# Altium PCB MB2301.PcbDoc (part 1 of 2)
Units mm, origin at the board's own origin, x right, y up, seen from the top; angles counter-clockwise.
Board outline 43 x 51.45 mm, 4 copper layers (Top Layer, Internal 1, Internal 2, Bottom Layer), stack 1.565 mm thick; 103 components, 91 nets, 383 pads, 756 vias.
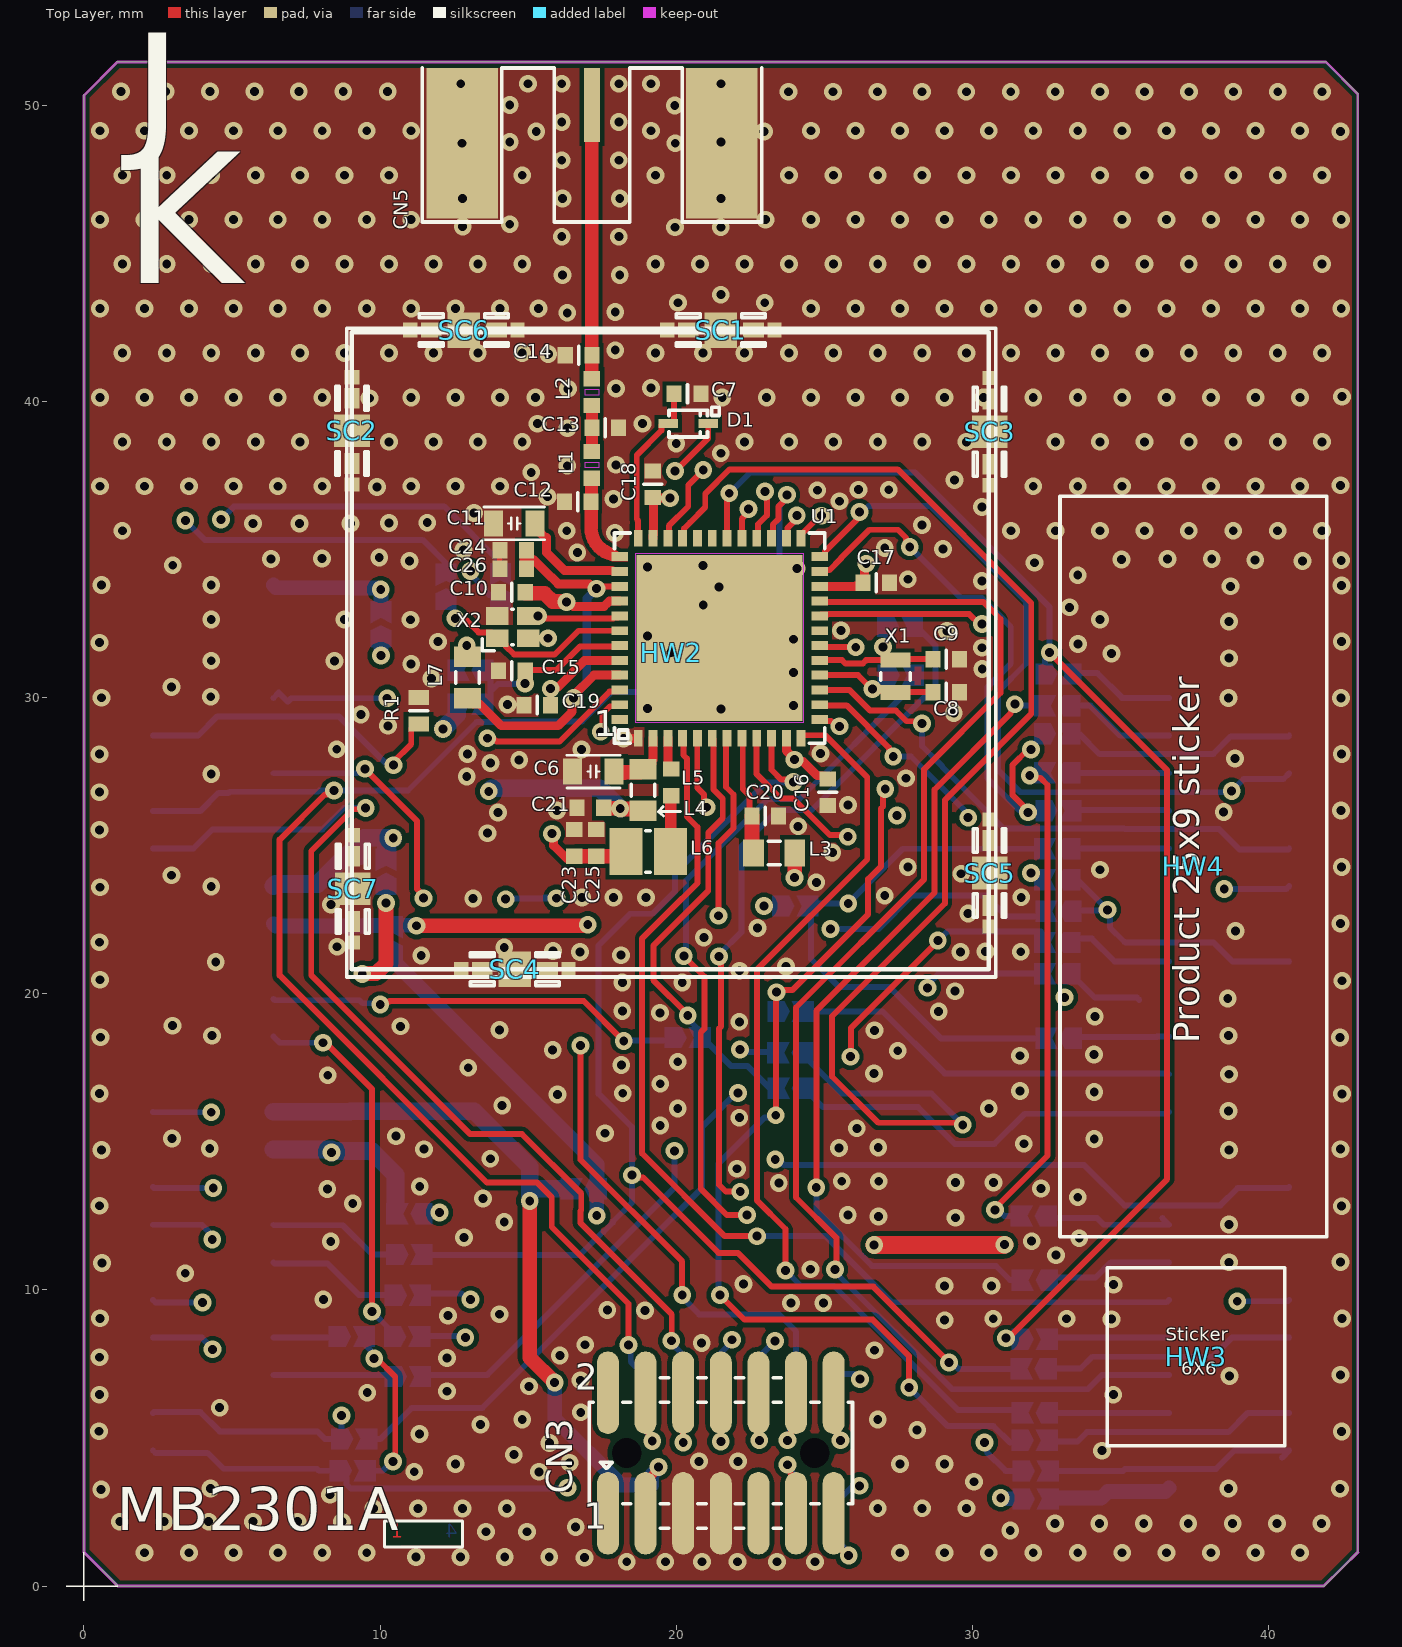
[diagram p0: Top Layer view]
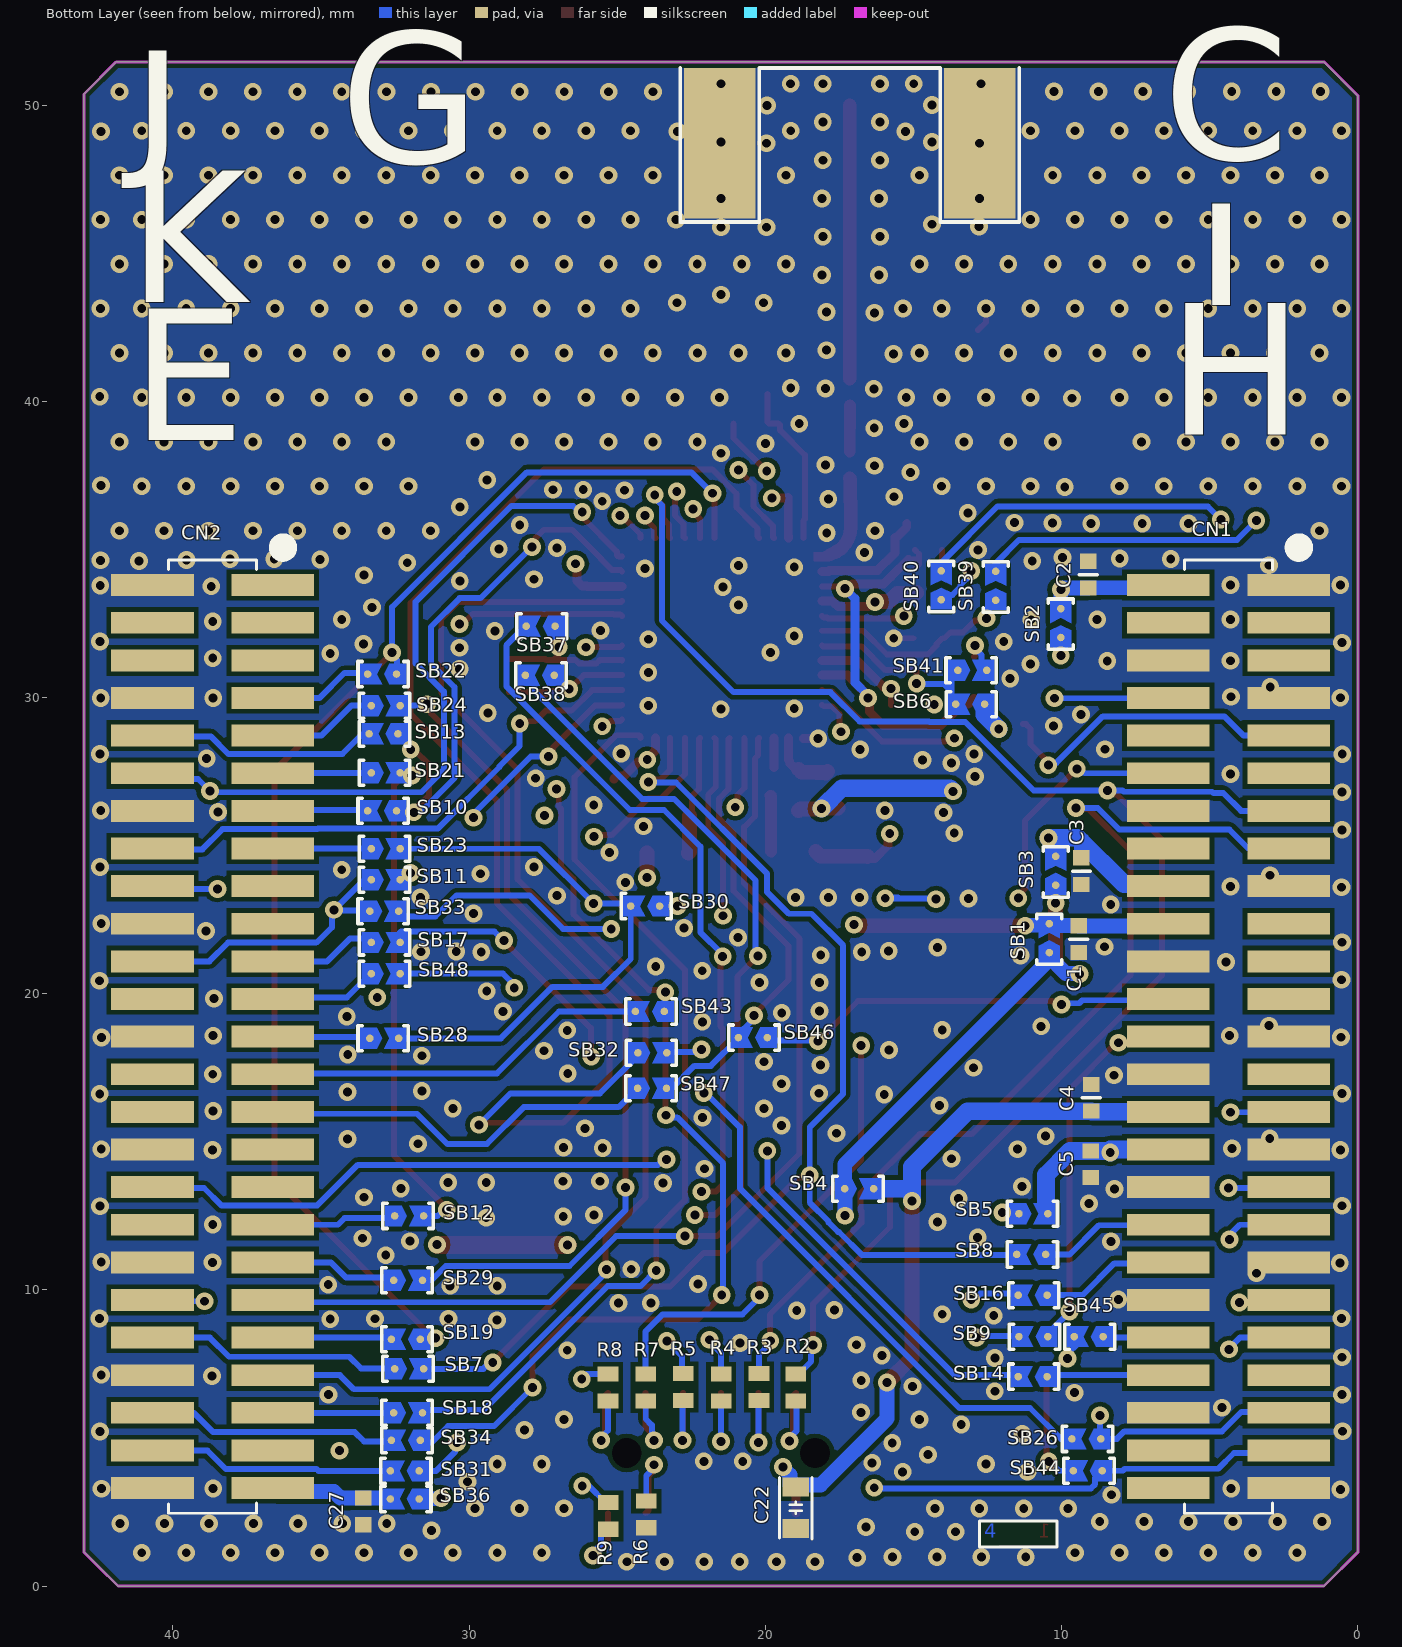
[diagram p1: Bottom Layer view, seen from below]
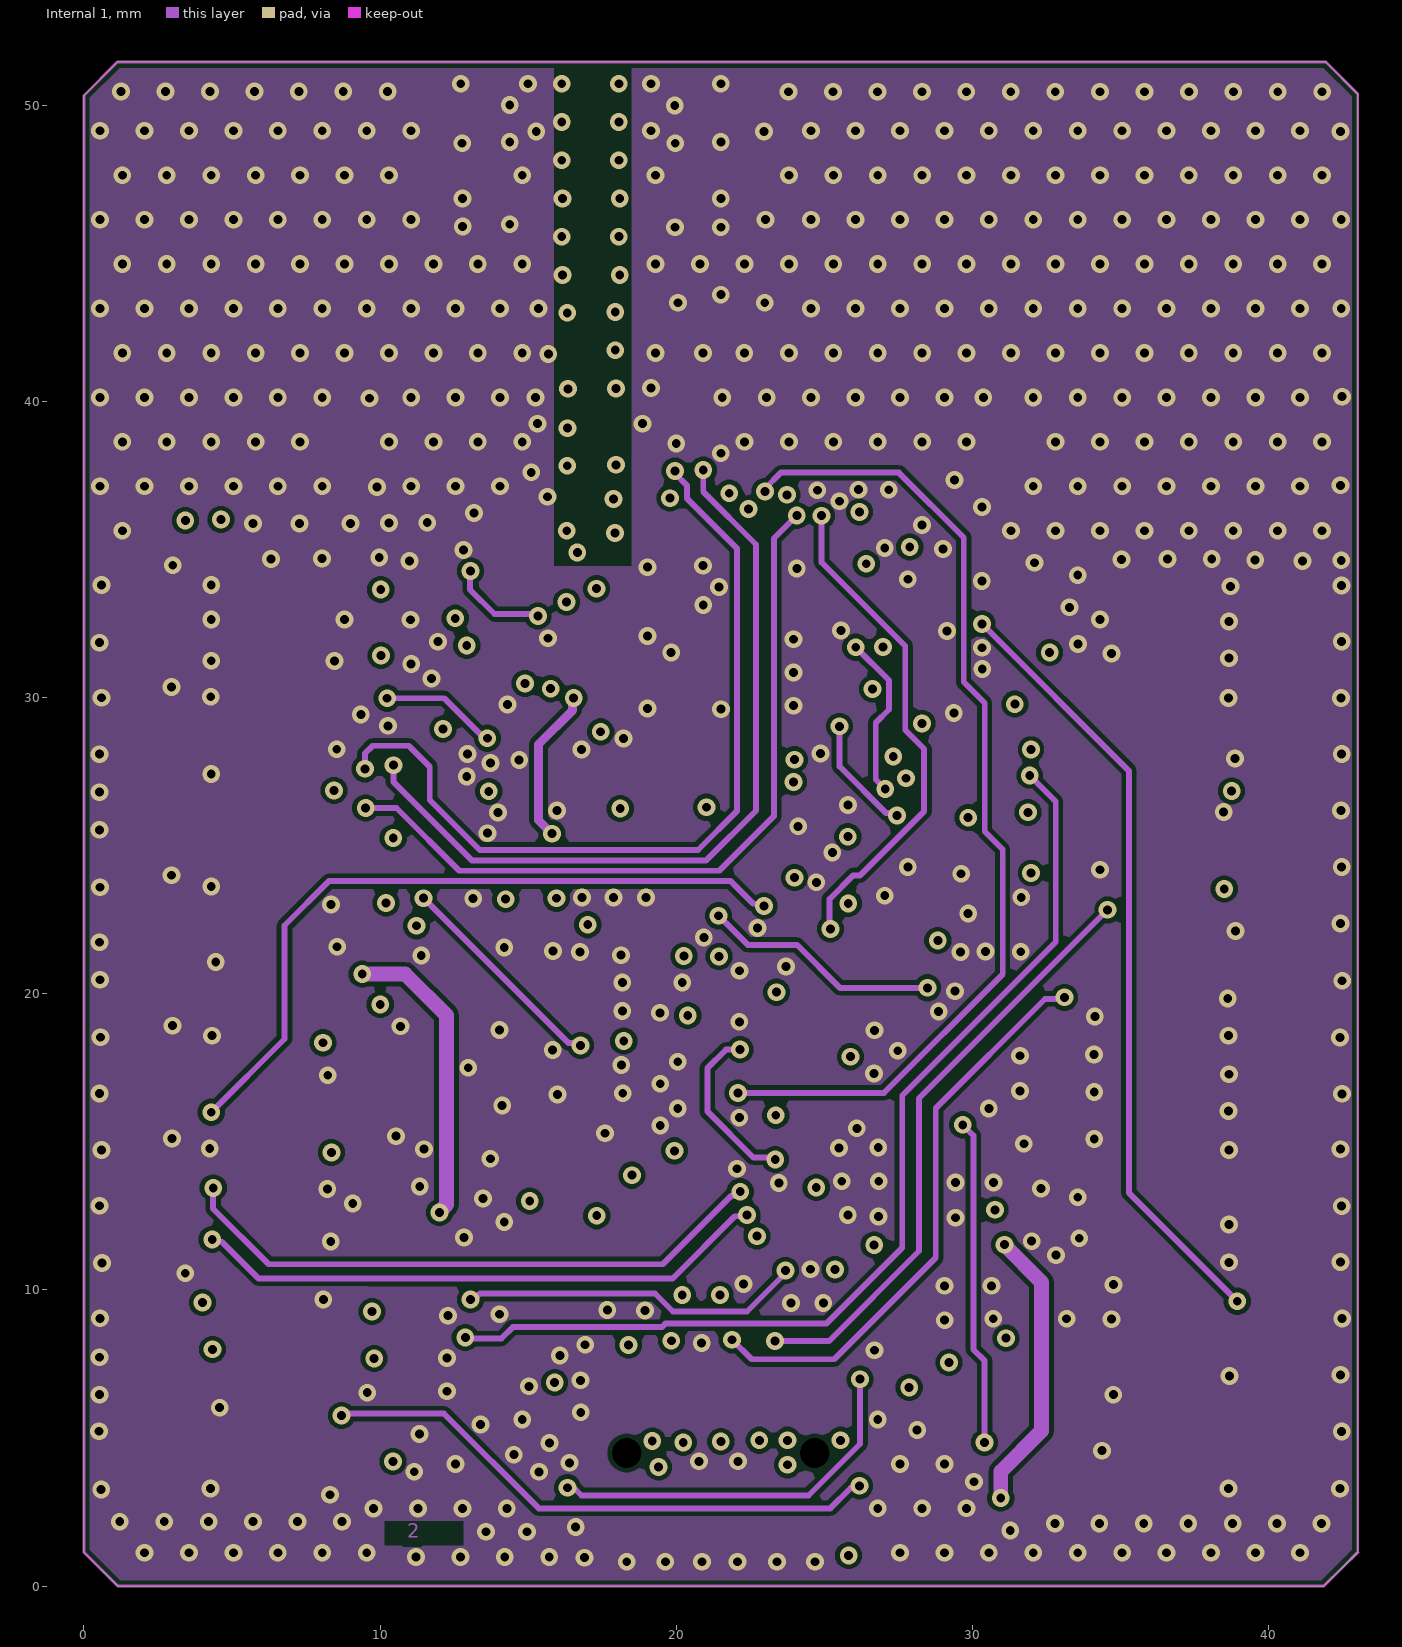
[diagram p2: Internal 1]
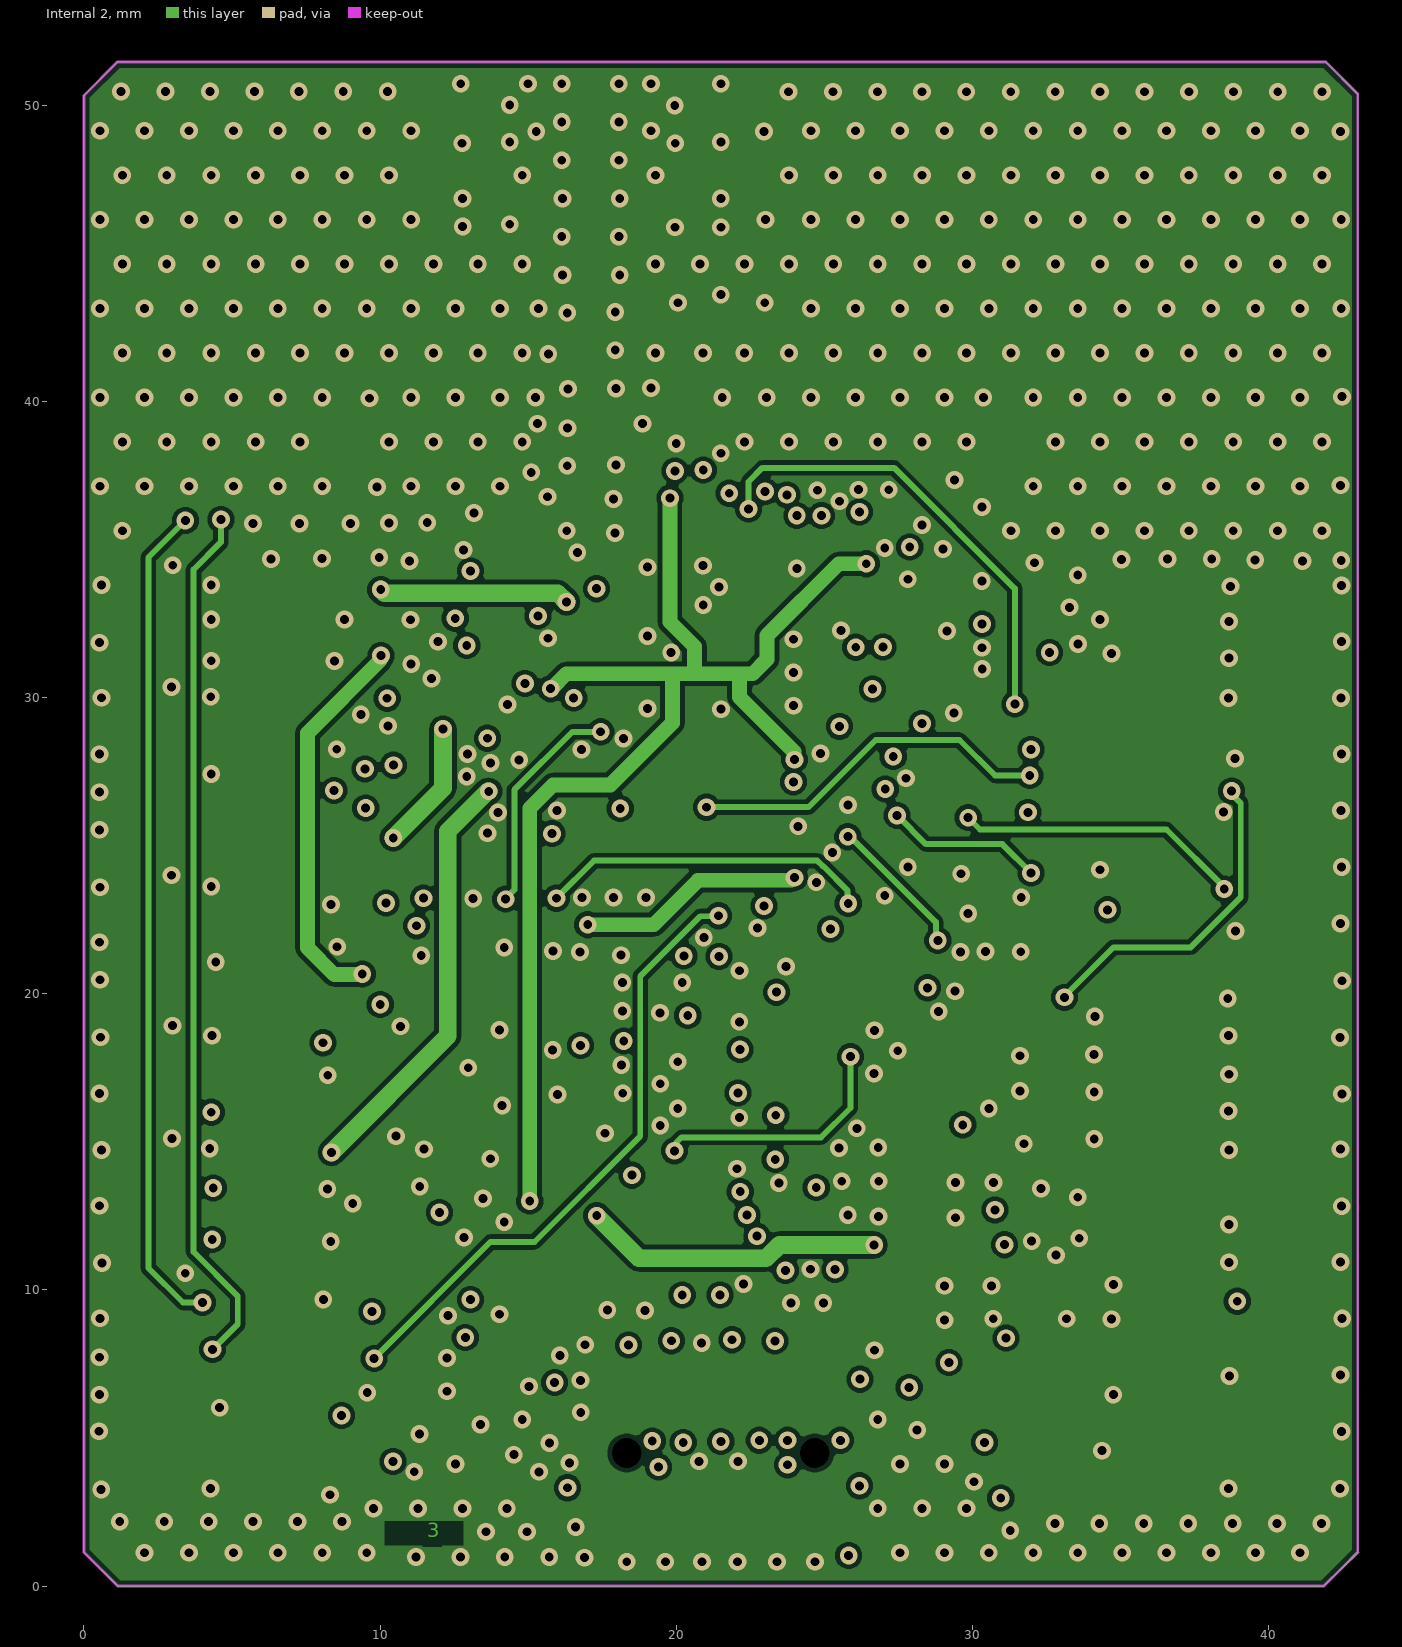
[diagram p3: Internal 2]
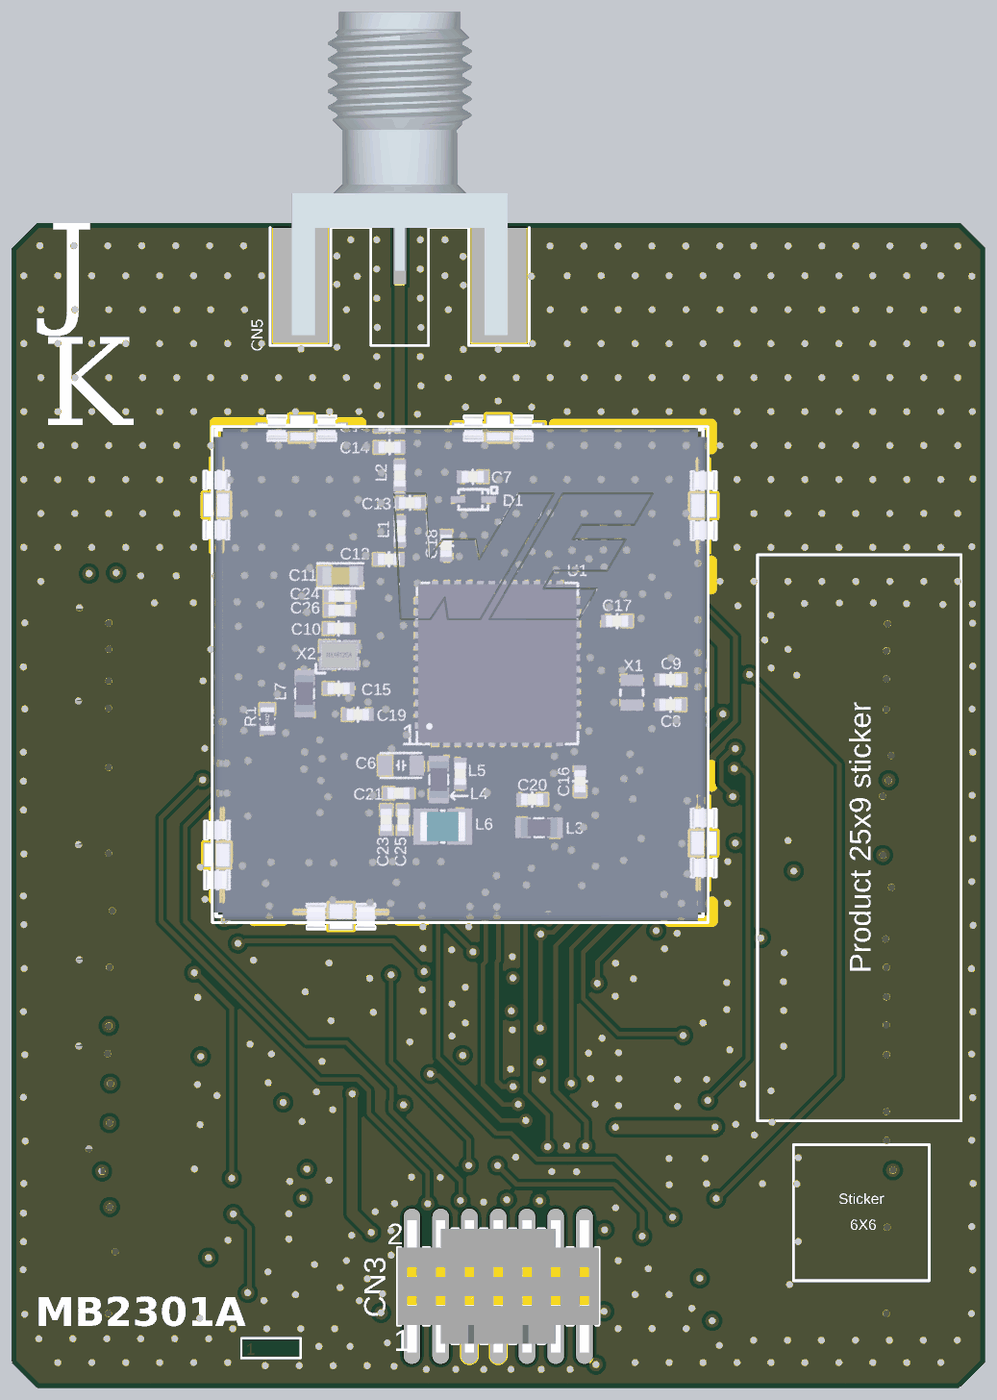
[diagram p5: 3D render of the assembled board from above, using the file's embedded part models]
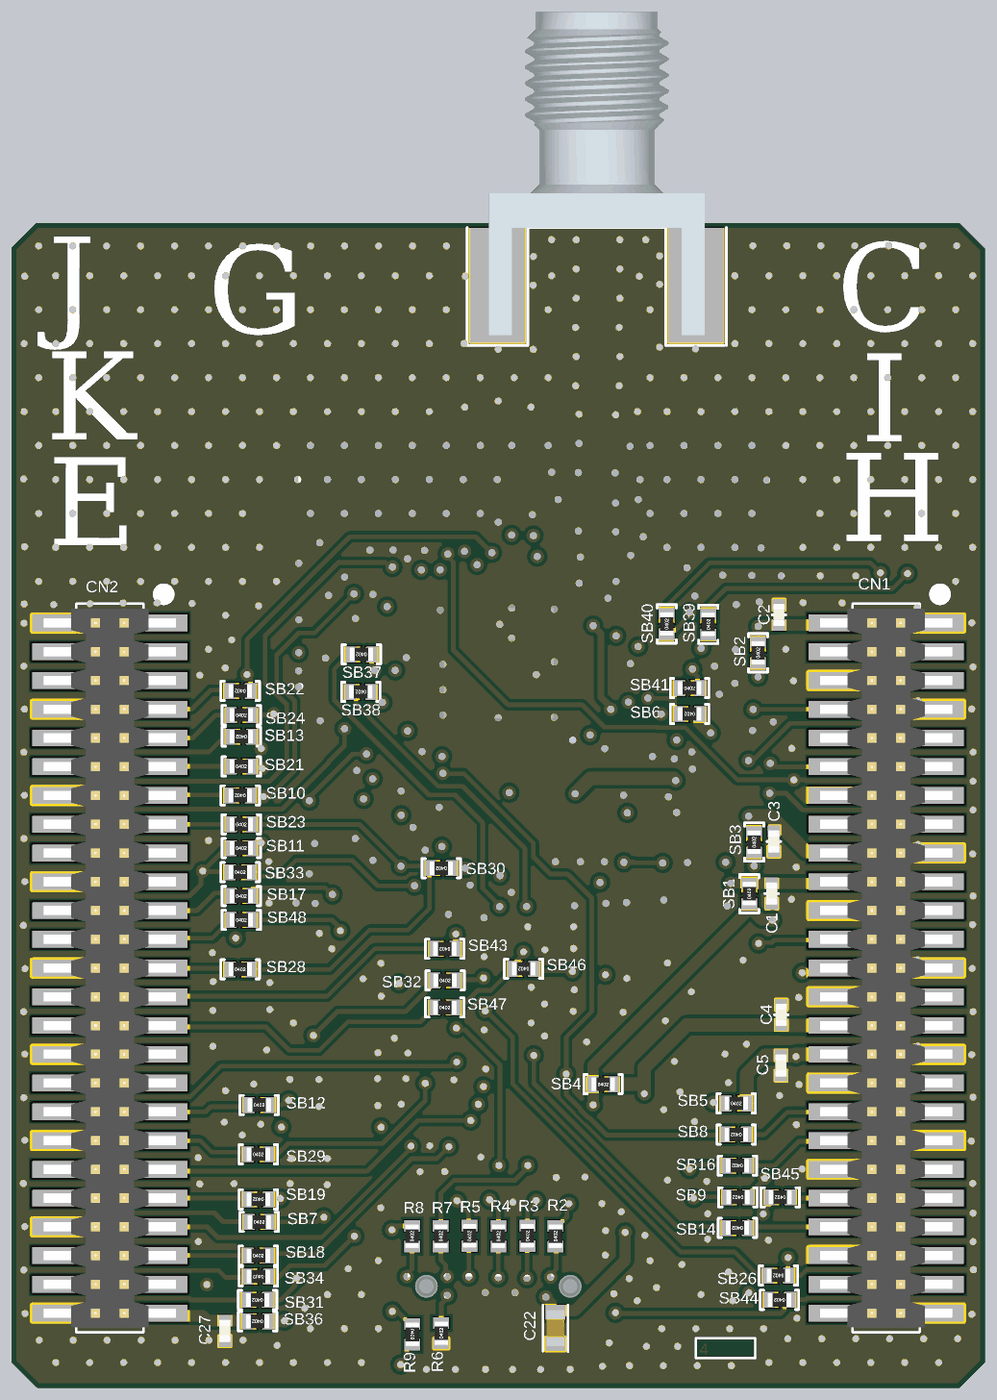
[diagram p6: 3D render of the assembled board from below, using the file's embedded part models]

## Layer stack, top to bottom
Top Solder: solder mask 0.0178, Solder Resist, Dk 4.2
Top Layer: signal copper 0.0406
Dielectric 1: prepreg 0.0762, FR-4, Dk 3.7
Internal 1: signal copper 0.0305
Dielectric 3: core 1.27, FR-4, Dk 4.5
Internal 2: signal copper 0.0305
Dielectric 2: prepreg 0.0762, FR-4, Dk 3.7
Bottom Layer: signal copper 0.0406
Bottom Solder: solder mask 0.0178, Solder Resist, Dk 4.2

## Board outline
0.001,1.143 0.001,50.3 0.001,50.324 1.132,51.455 41.913,51.455 43.001,50.367 43.001,39.986 43.002,1.145 41.852,0.005 1.139,0.005

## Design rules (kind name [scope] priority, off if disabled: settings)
Clearance RF [All vs (ObjectKind = 'Track') And (Net = 'NetC14_1') Or (Net = 'NetC13_2') Or (Net = 'NetC12_1')] p1: gap=0.13 ignorepadtopadclearanceinfootprint=FALSE
Clearance [All] p2: gap=0.15 ignorepadtopadclearanceinfootprint=FALSE
ComponentClearance [Not InComponent('HW2') vs Not InComponent('SC1') and InComponent('SC2') and InComponent('SC3') and InComponent('SC4') and InComponent('SC5')] p1: gap=0.2 collisioncheckmode=3 verticalgap=0.2 showdistances=FALSE
DiffPairsRouting [All] p1: maxlimit=0.254 minlimit=0.15 mostfreqgap=0.226 toplayer_minwidth=0.155 toplayer_maxwidth=0.226 toplayer_prefwidth=0.155 midlayer1_prefgap=0.15 midlayer1_minwidth=0.083 midlayer1_maxwidth=0.127 midlayer1_prefwidth=0.1 midlayer2_prefgap=0.15 midlayer2_minwidth=0.083 midlayer2_maxwidth=0.127 midlayer2_prefwidth=0.1 bottomlayer_minwidth=0.155 bottomlayer_maxwidth=0.226 bottomlayer_prefwidth=0.155 maxuncoupledlength=12.7
HoleSize [All] p1: absolutevalues=TRUE maxlimit=10 minlimit=0.025 maxpercent=80.000 minpercent=20.000
LayerPairs [All] p1 off: enforce=TRUE
MinimumSolderMaskSliver [All] p1 off: minsoldermaskwidth=0.1
PasteMaskExpansion [All] p1 off: expansion=0
PlaneConnect [All] p1: planeconnectstyle=Relief reliefexpansion=0.508 reliefentries=4 reliefconductorwidth=0.21 reliefairgap=0.21
PolygonConnect Path_RF [InNet('NetC12_2')] p1: connectstyle=Direct reliefconductorwidth=0.254 reliefentries=4 polygonreliefangle="90 Angle" airgapwidth=0.254
PolygonConnect PolygonConnect_via [IsVia] p2: connectstyle=Direct reliefconductorwidth=0.254 reliefentries=4 polygonreliefangle="90 Angle" airgapwidth=0.254
PolygonConnect General [All] p3: connectstyle=Direct reliefconductorwidth=0.2 reliefentries=4 polygonreliefangle="90 Angle" airgapwidth=0.2
RoutingVias [All] p1: holewidth=0.3 width=0.8 viastyle="Through Hole" minholewidth=0.2 minwidth=0.5 maxholewidth=3.5 maxwidth=6.5
SilkToSilkClearance [All] p1 off: silktosilkclearance=0.2
SilkToSolderMaskClearance [IsPad] p1 off: minsilkscreentomaskgap=0.2 clearancetoexposedcopper=TRUE
SolderMaskExpansion [All] p1: expansion=0.102 istentingtop=FALSE
SupplyNets "Schematic Supply Nets_6" [InNet('VDD3')] p1: voltage=0.000
SupplyNets "Schematic Supply Nets_5" [InNet('VDDA')] p2: voltage=0.000
SupplyNets "Schematic Supply Nets_4" [InNet('GND')] p3: voltage=0.000
SupplyNets "Schematic Supply Nets_3" [InNet('VDD1')] p4: voltage=0.000
SupplyNets "Schematic Supply Nets_2" [InNet('VDD14')] p5: voltage=0.000
SupplyNets "Schematic Supply Nets_1" [InNet('VDD4')] p6: voltage=0.000
SupplyNets "Schematic Supply Nets" [InNet('VDD5')] p7: voltage=0.000
Width [All] p1: maxlimit=6 minlimit=0.15 preferedwidth=0.254 toplayer_prefwidth=0.2 midlayer1_minwidth=0.2 midlayer1_maxwidth=1 midlayer2_minwidth=0.2 midlayer2_maxwidth=1 bottomlayer_prefwidth=0.2 minimp=50.000000 maximp=50.000000 favimp=50.000000
21 further rules are at their usual default settings.

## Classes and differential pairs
net class VDD4: VDD4
net class SWDIO: GPIO5/JTMS/SWDIO
net class SWCLK: GPIO6/JTCK/SWCLK
net class X2: NetSB39_1 NetSB40_1 OSC_IN OSC_OUT
net class X1: GPIO15/OSC32_IN GPIO16/OSC32_OUT NetC8_1 NetC9_2
net class DC/DC: NetC23_2 NetL5_2 NetL7_2
component class "STM32 microcontroller I/Os & Clock": C1 C2 C3 C4 C5 C7 C8 C9 C27 CN1 CN2 D1 R1 SB1 SB2 SB3 SB4 SB5 SB7 SB8 SB9 SB10 SB11 SB12 SB13 SB14 SB16 SB17 SB18 SB19 SB21 SB22 SB23 SB24 SB26 SB28 SB29 SB30 SB31 SB32 SB33 SB34 SB36 SB36: SB37 SB38 SB39 SB40 SB43 SB44 SB45 SB46 SB47 SB48 U1 X1 X2
component class "RF & Power Management Schematic": C6 C10 C11 C12 C13 C14 C15 C16 C17 C18 C19 C20 C21 C22 C23 C24 C25 C26 CN3 CN5 HW2 L1 L2 L3 L4 L5 L6 L7 R2 R3 R4 R5 R6 R7 R8 R9 SB6 SB41 SC1 SC2 SC3 SC4 SC5 SC6 SC7
component class Project_Overview: HW2 HW3 HW4

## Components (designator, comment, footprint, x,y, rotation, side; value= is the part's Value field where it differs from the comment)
C1 "Capacitor" C0402 9.422,21.843 r90 bottom value=1uF
C2 "Capacitor" C0402 9.1,34.15 r270 bottom value=1uF
C3 "Capacitor" C0402 9.329,24.142 r90 bottom value=1uF
C4 "Capacitor" C0402 9.001,16.486 r270 bottom value=1uF
C5 "Capacitor" C0402 9.013,14.247 r90 bottom value=1uF
C6 "Capacitor" C0603_H0P8 17.2,27.5 r180 top value=10µF
C7 "Capacitor" C0402 20.375,40.25 r180 top value=100nF
C8 "Capacitor" C0402 29.11,30.18 r0 top value=6pF
C9 "Capacitor" C0402 29.113,31.295 r180 top value=6pF
C10 "Capacitor" C0402 14.45,33.55 r180 top value=100nF
C11 "Capacitor" C0603 14.525,35.875 r0 top value=470nF
C12 "Capacitor" C0402 16.671,36.605 r180 top value=1.5pF
C13 "Capacitor" C0402 17.6,39.1 r180 top value=1.8pF
C14 "Capacitor" C0402 16.7,41.55 r180 top value=1pF
C15 "Capacitor" C0402 14.45,30.903 r180 top value=100nF
C16 "Capacitor" C0402 25.111,26.802 r270 top value=100nF
C17 "Capacitor" C0402 26.75,33.875 r0 top value=100nF
C18 "Capacitor" C0402 19.2,37.2 r90 top value=100nF
C19 "Capacitor" C0402 15.3,29.745 r180 top value=100nF
C20 "Capacitor" C0402 23,26 r180 top value=1uF
C21 "Capacitor" C0402 17.1,26.275 r180 top value=1uF
C22 "Capacitor" C0603 18.975,2.65 r90 bottom value=1uF
C23 "Capacitor" C0402 16.55,25.092 r270 top value=4.7uF
C24 "Capacitor" C0402 14.492,34.976 r180 top value=100nF
C25 "Capacitor" C0402 17.3,25.092 r90 top value=2.2uF
C26 "Capacitor" C0402 14.492,34.351 r180 top value=100nF
C27 "Capacitor" C0402 33.575,2.525 r90 bottom value=1uF
CN1 "FTSH-125-02-L-DV" FTSH-125-02-L-DV 4.367,18.553 r180 bottom locked
CN2 "FTSH-125-02-L-DV" FTSH-125-02-L-DV 38.657,18.553 r180 bottom locked
CN3 "Header 7x2" CON_SAMTEC_FTSH-107-01-L-DV-K-A 21.5,4.497 r0 top
CN5 "SMA-J-P-H-ST-EM1" 142-0701-851 17.15,48.75 r0 top value=Jack_SMA_142-0701-851
D1 "SCHOTTKY_1A_2K" DIO_SOD523_1A_2K 20.4,39.244 r0 top value=BAT54KFILM
HW2 "Shield Cover" SHIELD_WURTH_36003200_21P8X21P8 19.824,31.515 r0 top value=36003200
HW3 "STICKER_ES" STICKER_ES_6X6 37.542,7.747 r0 top value=N/A
HW4 "STICKER_PRODUCT" STICKER_PRODUCT_25X9 37.45,24.3 r90 top value=N/A
L1 "Inductor" C0402 17.15,37.85 r90 top value=3.3nH
L2 "Inductor" C0402 17.145,40.308 r90 top value=3.3nH
L3 "Inductor" IND_0603_H0P8 23.3,24.75 r180 top value="47R @ 100MHz"
L4 "Inductor" IND_0603_H0P8 18.875,26.875 r270 top value="47R @ 100MHz"
L5 "Inductor" C0402 19.824,27.133 r270 top value=10nH
L6 "Inductor" L0805_H0P9 19.05,24.8 r180 top value=2.2uH
L7 "Inductor" IND_0603_H0P8 12.95,30.675 r90 top value="47R @ 100MHz"
R1 "Resistor" R0402 11.3,29.55 r90 top value=100K
R2 "Resistor" R0402 18.975,6.708 r90 bottom value=47R
R3 "Resistor" R0402 20.211,6.726 r90 bottom value=47R
R4 "Resistor" R0402 21.49,6.708 r90 bottom value=47R
R5 "Resistor" R0402 22.77,6.726 r90 bottom value=47R
R6 "Resistor" R0402 24.018,2.425 r90 bottom value=47R
R7 "Resistor" R0402 24.04,6.708 r90 bottom value=47R
R8 "Resistor" R0402 25.31,6.708 r90 bottom value=47R
R9 "Resistor" R0402 25.3,2.375 r270 bottom value=47R
SB1 "SB_ON" SOLDER-BRIDGE_R0402-0R 10.413,21.839 r90 bottom
SB2 "SB_ON" SOLDER-BRIDGE_R0402-0R 10.025,32.475 r90 bottom
SB3 "SB_ON" SOLDER-BRIDGE_R0402-0R 10.2,24.113 r90 bottom
SB4 "SB_ON" SOLDER-BRIDGE_R0402-0R 16.87,13.419 r180 bottom
SB5 "SB_ON" SOLDER-BRIDGE_R0402-0R 10.988,12.574 r180 bottom
SB6 "SB_ON" SOLDER-BRIDGE_R0402-0R 13.05,29.775 r0 bottom
SB7 "SB_ON" SOLDER-BRIDGE_R0402-0R 32.059,7.339 r180 bottom
SB8 "SB_ON" SOLDER-BRIDGE_R0402-0R 10.988,11.199 r0 bottom
SB9 "SB_ON" SOLDER-BRIDGE_R0402-0R 10.914,8.425 r0 bottom
SB10 "SB_ON" SOLDER-BRIDGE_R0402-0R 32.9,26.173 r0 bottom
SB11 "SB_ON" SOLDER-BRIDGE_R0402-0R 32.851,23.85 r180 bottom
SB12 "SB_ON" SOLDER-BRIDGE_R0402-0R 32.059,12.5 r180 bottom
SB13 "SB_ON" SOLDER-BRIDGE_R0402-0R 32.851,28.775 r0 bottom
SB14 "SB_ON" SOLDER-BRIDGE_R0402-0R 10.938,7.076 r0 bottom
SB16 "SB_ON" SOLDER-BRIDGE_R0402-0R 10.938,9.825 r0 bottom
SB17 "SB_ON" SOLDER-BRIDGE_R0402-0R 32.851,21.732 r180 bottom
SB18 "SB_ON" SOLDER-BRIDGE_R0402-0R 32.097,5.853 r180 bottom
SB19 "SB_ON" SOLDER-BRIDGE_R0402-0R 32.097,8.336 r0 bottom
SB21 "SB_ON" SOLDER-BRIDGE_R0402-0R 32.851,27.458 r180 bottom
SB22 "SB_ON" SOLDER-BRIDGE_R0402-0R 32.9,30.79 r0 bottom
SB23 "SB_ON" SOLDER-BRIDGE_R0402-0R 32.851,24.894 r180 bottom
SB24 "SB_ON" SOLDER-BRIDGE_R0402-0R 32.851,29.725 r180 bottom
SB26 "SB_ON" SOLDER-BRIDGE_R0402-0R 9.126,4.973 r0 bottom
SB28 "SB_ON" SOLDER-BRIDGE_R0402-0R 32.9,18.495 r180 bottom
SB29 "SB_ON" SOLDER-BRIDGE_R0402-0R 32.097,10.325 r180 bottom
SB30 "SB_ON" SOLDER-BRIDGE_R0402-0R 24.018,22.96 r0 bottom
SB31 "SB_ON" SOLDER-BRIDGE_R0402-0R 32.134,3.893 r0 bottom
SB32 "SB_ON" SOLDER-BRIDGE_R0402-0R 23.85,18.008 r180 bottom
SB33 "SB_ON" SOLDER-BRIDGE_R0402-0R 32.9,22.786 r180 bottom
SB34 "SB_ON" SOLDER-BRIDGE_R0402-0R 32.097,4.925 r0 bottom
SB36 "SB_ON" SOLDER-BRIDGE_R0402-0R 32.134,2.945 r0 bottom
SB37 "SB_ON" SOLDER-BRIDGE_R0402-0R 27.548,32.407 r0 bottom
SB38 "SB_ON" SOLDER-BRIDGE_R0402-0R 27.575,30.75 r0 bottom
SB39 "SB_ON" SOLDER-BRIDGE_R0402-0R 12.225,33.732 r90 bottom
SB40 "SB_ON" SOLDER-BRIDGE_R0402-0R 14.063,33.75 r90 bottom
SB41 "SB_ON" SOLDER-BRIDGE_R0402-0R 13.051,30.917 r180 bottom
SB43 "SB_ON" SOLDER-BRIDGE_R0402-0R 23.861,19.402 r0 bottom
SB44 "SB_ON" SOLDER-BRIDGE_R0402-0R 9.079,3.898 r0 bottom
SB45 "SB_ON" SOLDER-BRIDGE_R0402-0R 9.048,8.425 r0 bottom
SB46 "SB_ON" SOLDER-BRIDGE_R0402-0R 20.382,18.52 r0 bottom
SB47 "SB_ON" SOLDER-BRIDGE_R0402-0R 23.861,16.809 r180 bottom
SB48 "SB_ON" SOLDER-BRIDGE_R0402-0R 32.851,20.678 r180 bottom
SC1 "Shield-clip_S0951-46R" CLIP_HARWIN_S0951-46R 21.5,42.4 r180 top value=S0951-46R
SC2 "Shield-clip_S0951-46R" CLIP_HARWIN_S0951-46R 9.05,39 r270 top value=S0951-46R
SC3 "Shield-clip_S0951-46R" CLIP_HARWIN_S0951-46R 30.575,38.975 r90 top value=S0951-46R
SC4 "Shield-clip_S0951-46R" CLIP_HARWIN_S0951-46R 14.55,20.825 r180 top value=S0951-46R
SC5 "Shield-clip_S0951-46R" CLIP_HARWIN_S0951-46R 30.575,24.075 r270 top value=S0951-46R
SC6 "Shield-clip_S0951-46R" CLIP_HARWIN_S0951-46R 12.825,42.4 r180 top value=S0951-46R
SC7 "Shield-clip_S0951-46R" CLIP_HARWIN_S0951-46R 9.077,23.542 r90 top value=S0951-46R
U1 "IC_STM32WBA23CEU7" ICC_UFQFPN48-EPAD_7X7_H0P55_P050 21.461,32.003 r90 top locked value=STM32WBA23CEU7
X1 "XTAL_2_PINS" CRY_NX1610SE_2P 27.398,30.715 r270 top value=32.768kHz
X2 "XTAL_4_PINS" CRY_NX1612SA_4P 14.475,32.375 r0 top value=32MHz

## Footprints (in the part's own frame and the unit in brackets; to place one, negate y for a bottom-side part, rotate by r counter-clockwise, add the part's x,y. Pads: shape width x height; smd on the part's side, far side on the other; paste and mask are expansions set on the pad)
142-0701-851 [mm]
  rect 0.55x2.5 smd mask+0.05: 1(0,1.25)
  rect 2.413x5.08 smd mask+0.05: 2(4.381,-0.04) 3(-4.381,-0.04)
  rect 2.413x5.08 smd far side mask+0.05: 4(-4.381,-0.04) 5(4.381,-0.04)
  silkscreen extent -5.72,-2.7 5.72,2.5, body extent -4.8,-2.25 4.8,12.05, height 4.08
C0402 [mm]
  rect 0.51x0.56 smd mask+0.05: 1(-0.45,0) 2(0.45,0)
  silkscreen extent 0,-0.3 0,0.3, body extent -0.5,-0.3 0.5,0.3, height 0.4
C0603 [mm]
  rect 0.64x0.89 smd mask+0.05: 1(-0.7,0) 2(0.7,0)
  silkscreen extent -1.05,-0.55 1.02,0.55, body extent -0.9,-0.5 0.9,0.5, height 1.4
C0603_H0P8 [mm] "MCD-01540"
  rect 0.64x0.89 smd mask+0.05: 1(-0.7,0) 2(0.7,0)
  silkscreen extent -0.9,-0.55 0.9,0.55, body extent -0.9,-0.5 0.9,0.5, height 1
CLIP_HARWIN_S0951-46R [mm] "MCD-01587_CLIP-X1"
  rect 0.48x0.5 smd mask+0.1: 1(-1.81,0) 1(1.81,0)
  rect 0.7x0.5 smd mask+0.1: 1(-1.1,0) 1(1.1,0)
  rect 1.1x1.2 smd mask+0.1: 1(0,0)
  silkscreen extent -1.5,-0.55 1.5,0.55, body extent -2.05,-0.65 2.05,0.65, height 1.28
CON_SAMTEC_FTSH-107-01-L-DV-K-A [mm] "MCD-01959"
  oval 0.74x2.79 smd mask+0.05: 1(-3.81,-2.035) 2(-3.81,2.035) 3(-2.54,-2.035) 4(-2.54,2.035) 5(-1.27,-2.035) 6(-1.27,2.035) 7(0,-2.035) 8(0,2.035) 9(1.27,-2.035) 10(1.27,2.035) 11(2.54,-2.035) 12(2.54,2.035) 13(3.81,-2.035) 14(3.81,2.035)
  round 0 hole 1 unplated paste-2539.97 mask+0.05: NPTH1(-3.175,0) NPTH2(3.175,0)
  silkscreen extent -4.44,-2.54 4.44,2.54, body extent -4.44,-2.92 4.45,2.92, height 6.12
CRY_NX1610SE_2P [mm] "MCD-02291"
  rect 0.5x1 smd mask+0.05: 1(-0.55,0) 2(0.55,0)
  silkscreen extent -0.13,-0.5 0.13,0.5, body extent -0.8,-0.5 0.8,0.5, height 0.45
CRY_NX1612SA_4P [mm] "MCD-02262"
  rect 0.75x0.6 smd mask+0.038: 1(-0.525,-0.375) 2(0.525,-0.375) 3(0.525,0.375) 4(-0.525,0.375)
  silkscreen extent -1.02,-0.8 0.02,0.6, body extent -0.8,-0.6 0.8,0.6, height 0.51
DIO_SOD523_1A_2K [mm] "MCD-01677"
  rect 0.65x0.3 smd mask+0.05: 1(-0.675,0) 2(0.675,0)
  silkscreen extent -0.65,-0.45 1.05,0.55, body extent -0.85,-0.45 0.85,0.45, height 0.71
FTSH-125-02-L-DV [mil] "Header2x25 Reverse 1.27mm SAMTEC (FTSH-125-02-L-DV)"
  rect 110x29.02 smd: 1(80,600) 2(-80,600) 3(80,550) 4(-80,550) 5(80,500) 6(-80,500) 7(80,450) 8(-80,450) 9(80,400) 10(-80,400) 11(80,350) 12(-80,350) 13(80,300) 14(-80,300) 15(80,250) 16(-80,250) 17(80,200) 18(-80,200) 19(80,150) 20(-80,150) 21(80,100) 22(-80,100) 23(80,50) 24(-80,50) 25(80,0) 26(-80,0) 27(80,-50) 28(-80,-50) 29(80,-100) 30(-80,-100) 31(80,-150) 32(-80,-150) 33(80,-200) 34(-80,-200) 35(80,-250) 36(-80,-250) 37(80,-300) 38(-80,-300) 39(80,-350) 40(-80,-350) 41(80,-400) 42(-80,-400) 43(80,-450) 44(-80,-450) 45(80,-500) 46(-80,-500) 47(80,-550) 48(-80,-550) 49(80,-600) 50(-80,-600)
  silkscreen extent -58,-633 103,659, body extent -115,-625 115,625, height 190
ICC_UFQFPN48-EPAD_7X7_H0P55_P050 [mm] "MCD-01704"
  rect 0.55x0.3 smd mask+0.05: 1(-3.375,2.75) 2(-3.375,2.25) 3(-3.375,1.75) 4(-3.375,1.25) 5(-3.375,0.75) 6(-3.375,0.25) 7(-3.375,-0.25) 8(-3.375,-0.75) 9(-3.375,-1.25) 10(-3.375,-1.75) 11(-3.375,-2.25) 12(-3.375,-2.75) 25(3.375,-2.75) 26(3.375,-2.25) 27(3.375,-1.75) 28(3.375,-1.25) 29(3.375,-0.75) 30(3.375,-0.25) 31(3.375,0.25) 32(3.375,0.75) 33(3.375,1.25) 34(3.375,1.75) 35(3.375,2.25) 36(3.375,2.75)
  rect 0.3x0.55 smd mask+0.05: 13(-2.75,-3.375) 14(-2.25,-3.375) 15(-1.75,-3.375) 16(-1.25,-3.375) 17(-0.75,-3.375) 18(-0.25,-3.375) 19(0.25,-3.375) 20(0.75,-3.375) 21(1.25,-3.375) 22(1.75,-3.375) 23(2.25,-3.375) 24(2.75,-3.375) 37(2.75,3.375) 38(2.25,3.375) 39(1.75,3.375) 40(1.25,3.375) 41(0.75,3.375) 42(0.25,3.375) 43(-0.25,3.375) 44(-0.75,3.375) 45(-1.25,3.375) 46(-1.75,3.375) 47(-2.25,3.375) 48(-2.75,3.375)
  rect 5.6x5.6 smd paste-2539.97 mask+0.05: 49(0,0)
  silkscreen extent -3.55,-3.55 3.55,3.55, body extent -3.5,-3.5 3.5,3.5, height 0.65
IND_0603_H0P8 [mm]
  rect 0.7x0.9 smd mask+0.05: 1(-0.7,0) 2(0.7,0)
  silkscreen extent -0.2,-0.4 0.2,0.4, body extent -0.8,-0.4 0.8,0.4, height 0.8
L0805_H0P9 [mm]
  rect 1.1x1.6 smd mask+0.05: 1(-0.75,0) 2(0.75,0)
  silkscreen extent -0.08,-0.7 0.08,0.7, body extent -1.07,-0.7 1.07,0.7, height 1.2
R0402 [mm]
  rect 0.51x0.7 smd mask+0.05: 1(-0.45,0) 2(0.45,0)
  silkscreen extent 0,-0.3 0,0.3, body extent -0.52,-0.3 0.52,0.3, height 0.4
SHIELD_WURTH_36003200_21P8X21P8 [mm] "MCD-04686"
  silkscreen extent -10.95,-10.95 10.95,10.95, body extent -10.9,-10.9 10.9,10.9, height 2.3
SOLDER-BRIDGE_R0402-0R [mil] "MCD-01619"
  round 10 smd paste-393.7: 1(-17.72,0) 2(20.67,0)
  Top Layer region: -30.51,-13.78 -30.51,13.78 -8.37,13.78 -1.48,0 -8.37,-13.78
  Top Layer region: 1.48,13.78 8.37,0 1.48,-13.78 30.51,-13.78 30.51,13.78
  silkscreen extent -33,-17 33,17, body extent -20,-12 20,12, height 14
STICKER_ES_6X6 [mm] "Sticker to mention board QR code 8X8"
  silkscreen extent -3,-3 3,3
STICKER_PRODUCT_25X9 [mm] "Sticker to mention board CPN code"
  silkscreen extent -12.5,-4.5 12.5,4.5

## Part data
C1 C2 C3 C4 C5 C20 C21 C27: library part MCD-01722, "Capacitor, MLCC, 1uF, 10V, X5R, +/-10%, 0402, T=0.5mm", Manufacturer=YAGEO, Manufacturer_Part_Number=CC0402KRX5R6BB105, Package=0402
C6: library part MCD-02733, "Capacitor, MLCC, 10uF, 10V, X6S, +/-20%, 0603, T=1mm", Manufacturer=MURATA, Manufacturer_Part_Number=GRM188C81A106MA73, Package=0603
C7 C10 C15 C16 C17 C18 C19 C24 C26: library part MCD-00006, "Capacitor, MLCC, 100nF, 16V, X7R, +/-10%, 0402, T=0.5mm", Alternate_Manufacturer=MURATA, Alternate_Manufacturer_Part_Number=GCM155R71C104KA55D, Manufacturer=YAGEO, Manufacturer_Part_Number=CC0402KRX7R7BB104, Package=C0402
C8 C9: library part MCD-03185, "Capacitor, MLCC, 6 pF, 50V, NPO, ±0,25pF, 0402, T=0.5mm", Manufacturer=MURATA, Manufacturer_Part_Number=GJM1555C1H6R0CB01, Package=0402
C11: library part MCD-01006, "Capacitor, MLCC, 470nF, 16V, X7R, +/-10%, 0603, T=0.8mm", Manufacturer=YAGEO, Manufacturer_Part_Number=CC0603KRX7R7BB474, Package=0603
C12: library part MCD-02994, "Capacitor, MLCC, 1.5pF, 50V, C0G, +/-0.25pF, 0402, T=0.5mm", Manufacturer=MURATA, Manufacturer_Part_Number=GRM1555C1H1R5CA01, Package=0402
C13: library part MCD-02995, "Capacitor, MLCC, 1.8pF, 50V, C0G, +/-0.25pF, 0402, T=0.5mm", Manufacturer=MURATA, Manufacturer_Part_Number=GRM1555C1H1R8CA01, Package=0402
C14: library part MCD-03045, "Capacitor, MLCC, 1.0pF, 50V, C0G, +/-0.25pF, 0402, T=0.5mm", Manufacturer=MURATA, Manufacturer_Part_Number=GRM1555C1H1R0CA01, Package=0402
C22: library part MCD-00010, "Capacitor, MLCC, 1uF, 16V, X5R, 10%, 0603, T=0,8mm", Manufacturer=YAGEO, Manufacturer_Part_Number=CC0603KRX5R7BB105, Package=C0603
C23: library part MCD-01356, "Capacitor, MLCC, 4.7uF, 6V3, X5R, +/-20%, 0402, T=0.5mm", Manufacturer=MURATA, Manufacturer_Part_Number=GRM155R60J475ME47, Package=0402
C25: library part MCD-01823, "Capacitor, MLCC, 2.2uF, 6V3, X5R,+/-10%, 0402, T=0.5mm", Manufacturer=MURATA, Manufacturer_Part_Number=GRM155R60J225KE95D, Package=0402
CN1 CN2: library part MCD-02746, "Header 25x2, 12.7mm, SMT,height 4.83mm", Manufacturer=SAMTEC
CN3: library part MCD-01531, "Header, 7x2, 1.27mm, VR, T=5.97mm, FTSH series STDC14 without Alignment Pin", Manufacturer=SAMTEC, Manufacturer_Part_Number=FTSH-107-01-L-DV-K
CN5: library part MCD-02072, "Jack_SMA, VR, PCB edge, 50R, T=7.92mm", Manufacturer=CINCH, Manufacturer_Part_Number=142-0701-851
D1: library part MCD-01677, "Small signal Schottky diodes", Manufacturer=STMICROELECTRONICS, Manufacturer_HQ_COO=EU, Manufacturer_Part_Number=BAT54KFILM, Package=SOD-523
HW2: library part MCD-04686, "RF Shield cover, 21.5x21.5x3.3mm", Manufacturer="WURTH ELEKTRONIK", Manufacturer_Part_Number=36003200
HW3: library part MCD-00234, "Sticker ES, 6x6mm", Manufacturer=N/A
HW4: library part MCD-00547, "Sticker product, 25x9mm", Manufacturer=N/A, Manufacturer_HQ_COO=Unknown
L1 L2: library part MCD-03001, "Inductor, 3.3nH, +/-0.3nH, 800 mA, 0.125Ohm, 0402, T=0.5mm", Manufacturer=MURATA, Manufacturer_Part_Number=LQG15HS3N3S02, Package=0402
L3 L4 L7: library part MCD-03831, "Ferrite bead, 47R @ 100MHz, +/-25%, 3.5A, 0R02, 0603, T=0.8mm", Manufacturer="TAIYO YUDEN", Manufacturer_Part_Number=LSMGA160808T470RG, Package=0603
L5: library part MCD-03035, "Inductor, 10nH, +/-2%, 500 mA, 0.26Ohm, 0402, T=0.5mm", Manufacturer=MURATA, Manufacturer_Part_Number=LQG15HS10NJ02D, Package=0402
L6: library part MCD-03791, "Inductor, 2.2uH, +/-20%, 1.8A, 0R138, 0805, T=0.8mm", Manufacturer=MURATA, Manufacturer_Part_Number=DFE21CCN2R2MELL, Package=0805
R1: library part MCD-00059, "Resistor, 100K, 0402, +/-1%, 1/16W", Manufacturer=YAGEO, Manufacturer_Part_Number=RC0402FR-07100KL, Package=0402
R2 R3 R4 R5 R6 R7 R8 R9: library part MCD-00481, "Resistor,47R,0402,1%,1/16W", Manufacturer=YAGEO, Manufacturer_Part_Number=RC0402FR-0747RL, Package=R0402
SB1 SB2 SB3 SB4 SB5 SB6 SB7 SB8 SB9 SB10 SB11 SB12 SB13 SB14 SB16 SB17 SB18 SB19 SB21 SB22 SB23 SB24 SB26 SB28 SB29 SB30 SB31 SB32 SB33 SB34 SB36 SB37 SB38 SB39 SB40 SB41 SB43 SB44 SB45 SB46 SB47 SB48: library part MCD-01618, "Solder Bridge 0402 ON", Manufacturer=YAGEO, Manufacturer_Part_Number=RC0402JR-070RL, Package=SB0402
SC1 SC2 SC3 SC4 SC5 SC6 SC7: library part MCD-01587, "shield clip Harwin S0951-46R to fix RF shielded cavity", Manufacturer=HARWIN, Manufacturer_Part_Number=S0951-46R
U1: library part MCD-04358, "MCU, ARM Cortex-M33 32-bit, 512KB Flash, 96KB RAM, Crypto, SMPS", Manufacturer=STMICROELECTRONICS, Manufacturer_Part_Number=STM32WBA23CEU7, Package=UFQFPN48
X1: library part MCD-02579, "Crystal, 32.768kHz, 6pF, +/-20ppm, 70KR, 1.6x1mm", Manufacturer=NDK, Manufacturer_Part_Number=NX1610SE-32.768KHZ-EXS00A-MU01501, Package=1.6x1mm
X2: library part MCD-02578, "Crystal, 32MHz, 8pF, +/-10ppm, 40R, 1612(metric), T=0.3mm", Manufacturer=NDK, Manufacturer_Part_Number=NX1612SA-32MHZ-EXS00A-CS09166, Package=1612(metric)

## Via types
v1: diameter 0.6, hole 0.3, Top Layer to Bottom Layer, tented both sides, 756 vias

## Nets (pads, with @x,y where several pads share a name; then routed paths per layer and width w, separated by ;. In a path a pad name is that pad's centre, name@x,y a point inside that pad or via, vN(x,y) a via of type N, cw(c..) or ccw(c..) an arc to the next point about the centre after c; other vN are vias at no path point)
GND: C1.1 C2.1 C3.1 C4.1 C5.1 C6.2 C7.1 C8.2 C9.1 C10.2 C11.1 C12.2 C13.1 C14.2 C15.2 C16.2 C17.2 C18.2 C19.2 C20.1 C21.2 C22.1 C23.1 C24.2 C25.2 C26.2 C27.1 CN1.1 CN1.6 CN1.7 CN1.14 CN1.17 CN1.22 CN1.25 CN1.28 CN1.31 CN1.34 CN1.37 CN1.40 CN1.46 CN1.49 CN2.2 CN2.8 CN2.14 CN2.20 CN2.26 CN2.32 CN2.38 CN2.44 CN2.50 CN3.5 CN3.7 CN5.2 CN5.3 CN5.4 CN5.5 R1.2 R6.1 SC1.1 SC2.1 SC3.1 SC4.1 SC5.1 SC6.1 SC7.1 U1.1 U1.49 X2.2 X2.4 | length 2.6
  Top Layer w0.2: v1(12.548,43.129) 12.548,42.677 SC6.1@12.825,42.4 ; C26.2@14.032,34.583 14.032,34.361 C26.2@14.042,34.351 ; C26.2@14.037,34.583 14.037,34.971 C24.2@14.042,34.976 ; X2.2@15,32 v1(15.664,32) ; v1(18.215,28.616) v1@18.222,28.622 ; U1.1@18.705,28.622 U1.1@18.711,28.628
  Top Layer w0.3: v1@18.222,28.622 U1.1@18.705,28.622
  other v1: 18.325,0.825 19.626,0.825 20.864,0.825 22.064,0.825 23.4,0.825 24.675,0.825 16.9,0.964 11.208,0.989 12.708,0.989 14.208,0.989 15.708,0.989 2.048,1.129 3.548,1.129 5.048,1.129 6.548,1.129 8.048,1.129 9.548,1.129 27.548,1.129 29.048,1.129 30.548,1.129 32.048,1.129 33.548,1.129 35.048,1.129 36.548,1.129 38.048,1.129 39.548,1.129 41.048,1.129 13.575,1.84 14.955,1.84 31.27,1.885 16.6,2 32.778,2.117 34.278,2.117 35.778,2.117 37.278,2.117 38.778,2.117 40.278,2.117 41.778,2.117 1.211,2.18 2.711,2.18 4.211,2.18 5.711,2.18 7.211,2.18 8.711,2.18 9.777,2.625 11.277,2.625 12.777,2.625 14.277,2.625 26.798,2.629 28.298,2.629 29.798,2.629 8.311,3.088 0.582,3.262 4.275,3.295 38.638,3.298 42.405,3.292 30.05,3.525 11.152,3.864 15.363,3.862 12.548,4.129 27.548,4.129 29.048,4.129 16.393,4.166 20.763,4.216 22.076,4.216 14.513,4.441 34.372,4.575 15.716,4.835 11.331,5.134 0.512,5.23 42.457,5.221 28.127,5.272 13.387,5.459 14.798,5.629 26.798,5.629 16.77,5.871 4.583,6.028 0.53,6.466 34.75,6.466 9.564,6.535 12.253,6.583 15.028,6.748 16.761,6.95 38.675,7.1 42.415,7.135 12.253,7.699 0.53,7.728 16.066,7.788 26.685,7.967 16.921,8.151 20.854,8.21 29.056,8.981 34.688,9.015 0.547,9.043 30.697,9.03 33.174,9.03 42.475,9.04 12.291,9.132 14.027,9.181 17.67,9.32 18.941,9.303 23.865,9.561 24.96,9.559 8.083,9.681 29.048,10.14 30.638,10.141 34.755,10.179 22.27,10.198 3.42,10.565 24.526,10.702 0.607,10.912 38.657,10.933 42.415,10.945 32.814,11.175 8.331,11.635 31.993,11.649 33.601,11.745 12.833,11.773 38.653,12.209 14.191,12.296 29.421,12.439 26.819,12.479 25.787,12.535 42.457,12.829 0.53,12.841 9.076,12.917 13.474,13.085 33.548,13.129 8.218,13.41 32.303,13.426 11.336,13.489 23.458,13.613 29.421,13.632 30.706,13.632 25.581,13.669 26.832,13.669 22.05,14.092 13.72,14.431 0.59,14.725 38.657,14.725 11.484,14.754 42.415,14.754 4.25,14.775 25.49,14.797 26.816,14.812 31.728,14.936 34.105,15.092 2.974,15.112 10.537,15.191 17.595,15.292 26.091,15.456 19.456,15.549 22.125,15.818 38.638,16.042 20.048,16.129 30.548,16.129 14.118,16.226 15.987,16.6 0.53,16.628 18.189,16.641 42.468,16.621 34.105,16.682 31.595,16.719 19.456,16.962 8.23,17.25 38.653,17.284 26.669,17.309 12.973,17.503 18.141,17.593 20.045,17.705 31.595,17.907 34.095,17.95 27.472,18.076 15.824,18.096 0.565,18.533 42.405,18.524 4.325,18.585 38.638,18.585 26.685,18.765 14.028,18.776 10.69,18.9 2.994,18.922 22.126,19.052 34.126,19.227 19.445,19.355 28.853,19.402 18.175,19.413 38.613,19.837 29.404,20.087 18.175,20.377 20.196,20.377 42.475,20.438 0.547,20.473 22.131,20.778 23.699,20.918 4.45,21.075 11.386,21.292 18.129,21.303 16.744,21.408 29.588,21.408 30.432,21.425 31.624,21.419 15.837,21.447 14.188,21.557 8.549,21.586 0.53,21.737 20.926,21.896 38.876,22.118 22.742,22.215 42.415,22.368 29.85,22.711 8.34,23.01 13.14,23.213 16.816,23.248 17.873,23.251 18.976,23.251 31.64,23.255 27.035,23.31 0.547,23.594 4.3,23.618 24.725,23.76 2.961,24.002 29.613,24.051 34.3,24.184 27.813,24.274 42.457,24.274 25.264,24.763 13.624,25.421 0.53,25.533 24.111,25.65 13.982,26.118 38.475,26.138 15.966,26.185 42.433,26.185 25.793,26.373 0.53,26.803 27.752,27.275 12.923,27.337 4.3,27.418 13.721,27.792 14.692,27.894 38.859,27.941 0.525,28.087 12.95,28.096 42.457,28.089 24.866,28.111 16.798,28.244 8.537,28.251 10.267,29.043 9.348,29.425 29.366,29.475 21.503,29.605 19.025,29.625 23.949,29.725 14.299,29.768 0.59,29.992 38.638,29.98 42.433,29.987 4.284,30.025 2.954,30.352 11.736,30.644 23.949,30.84 30.325,30.965 11.048,31.129 4.3,31.239 8.458,31.235 38.653,31.327 34.688,31.485 19.824,31.515 30.32,31.679 33.56,31.809 0.53,31.851 11.95,31.884 42.457,31.887 23.949,31.965 19.025,32.075 25.561,32.261 29.131,32.24 38.653,32.562 4.298,32.629 8.798,32.629 11.023,32.624 34.298,32.629 33.273,33.043 20.907,33.125 21.435,33.732 38.702,33.753 42.45,33.782 0.59,33.8 4.3,33.793 30.311,33.937 27.812,33.99 33.548,34.129 24.066,34.357 19.025,34.4 3.001,34.463 20.9,34.45 32.087,34.549 10.988,34.605 41.138,34.605 39.538,34.646 42.445,34.629 6.313,34.676 35.027,34.656 36.575,34.676 38.071,34.676 8.036,34.689 9.97,34.724 16.657,34.89 12.817,34.982 28.996,35.012 27.035,35.051 17.925,35.55 1.298,35.629 16.298,35.629 31.298,35.629 32.798,35.629 34.298,35.629 35.798,35.629 37.298,35.629 38.798,35.629 40.298,35.629 41.798,35.629 28.288,35.819 5.711,35.875 7.275,35.875 9.001,35.875 10.302,35.891 11.59,35.902 13.164,36.228 30.313,36.429 25.506,36.625 17.873,36.7 15.651,36.777 24.757,36.996 27.17,37.012 26.145,37.016 9.893,37.108 0.548,37.129 2.048,37.129 3.548,37.129 5.048,37.129 6.548,37.129 8.048,37.129 11.048,37.129 12.548,37.129 14.048,37.129 32.048,37.129 33.548,37.129 35.048,37.129 36.548,37.129 38.048,37.129 39.548,37.129 41.048,37.129 42.423,37.162 29.389,37.337 15.1,37.6 16.315,37.822 17.964,37.854 21.5,38.245 19.995,38.571 1.298,38.629 2.798,38.629 4.298,38.629 5.798,38.629 7.298,38.629 10.298,38.629 11.798,38.629 13.298,38.629 14.798,38.629 22.298,38.629 23.798,38.629 25.298,38.629 26.798,38.629 28.298,38.629 29.798,38.629 32.798,38.629 34.298,38.629 35.798,38.629 37.298,38.629 38.798,38.629 40.298,38.629 41.798,38.629 16.321,39.091 15.315,39.244 18.856,39.244 9.644,40.1 0.548,40.129 2.048,40.129 3.548,40.129 5.048,40.129 6.548,40.129 8.048,40.129 11.048,40.129 12.548,40.129 14.048,40.129 15.241,40.129 21.548,40.129 23.048,40.129 24.548,40.129 26.048,40.129 27.548,40.129 29.048,40.129 30.361,40.129 32.048,40.129 33.548,40.129 35.048,40.129 36.548,40.129 38.048,40.129 39.548,40.129 41.048,40.129 42.468,40.154 16.337,40.42 17.964,40.434 19.142,40.45 15.677,41.591 1.298,41.629 2.798,41.629 4.298,41.629 5.798,41.629 7.298,41.629 8.798,41.629 10.298,41.629 11.798,41.629 13.298,41.629 14.798,41.629 19.298,41.629 20.902,41.631 22.293,41.631 23.798,41.629 25.298,41.629 26.798,41.629 28.298,41.629 29.798,41.629 31.298,41.629 32.798,41.629 34.298,41.629 35.798,41.629 37.298,41.629 38.798,41.629 40.298,41.629 41.798,41.629 17.935,41.724 16.315,42.984 17.935,43.014 0.548,43.129 2.048,43.129 3.548,43.129 5.048,43.129 6.548,43.129 8.048,43.129 9.548,43.129 11.048,43.129 14.048,43.129 15.35,43.129 24.548,43.129 26.048,43.129 27.548,43.129 29.048,43.129 30.548,43.129 32.048,43.129 33.548,43.129 35.048,43.129 36.548,43.129 38.048,43.129 39.548,43.129 41.048,43.129 42.445,43.129 20.057,43.325 22.983,43.325 21.5,43.597 16.159,44.266 18.087,44.266 1.298,44.629 2.798,44.629 4.298,44.629 5.798,44.629 7.298,44.629 8.798,44.629 10.298,44.629 11.798,44.629 13.298,44.629 14.798,44.629 19.298,44.629 20.798,44.629 22.298,44.629 23.798,44.629 25.298,44.629 26.798,44.629 28.298,44.629 29.798,44.629 31.298,44.629 32.798,44.629 34.298,44.629 35.798,44.629 37.298,44.629 38.798,44.629 40.298,44.629 41.798,44.629 16.13,45.556 18.058,45.556 19.956,45.875 21.5,45.875 12.786,45.897 14.375,45.975 0.548,46.129 2.048,46.129 3.548,46.129 5.048,46.129 6.548,46.129 8.048,46.129 9.548,46.129 11.048,46.129 23.012,46.129 24.548,46.129 26.048,46.129 27.548,46.129 29.048,46.129 30.548,46.129 32.048,46.129 33.548,46.129 35.048,46.129 36.548,46.129 38.048,46.129 39.548,46.129 41.048,46.129 42.445,46.129 12.777,46.846 16.159,46.846 18.087,46.846 21.5,46.846 1.298,47.629 2.798,47.629 4.298,47.629 5.798,47.629 7.298,47.629 8.798,47.629 10.298,47.629 14.798,47.629 19.298,47.629 23.798,47.629 25.298,47.629 26.798,47.629 28.298,47.629 29.798,47.629 31.298,47.629 32.798,47.629 34.298,47.629 35.798,47.629 37.298,47.629 38.798,47.629 40.298,47.629 41.798,47.629 16.13,48.136 18.058,48.136 12.769,48.71 19.96,48.71 14.375,48.75 21.5,48.75 15.27,49.104 22.96,49.104 42.423,49.104 0.548,49.129 2.048,49.129 3.548,49.129 5.048,49.129 6.548,49.129 8.048,49.129 9.548,49.129 11.048,49.129 19.142,49.129 24.548,49.129 26.048,49.129 27.548,49.129 29.048,49.129 30.548,49.129 32.048,49.129 33.548,49.129 35.048,49.129 36.548,49.129 38.048,49.129 39.548,49.129 41.048,49.129 16.13,49.426 18.058,49.426 19.944,49.98 14.375,50 23.788,50.446 25.288,50.446 26.788,50.446 28.288,50.446 29.788,50.446 31.288,50.446 32.788,50.446 34.3,50.446 35.8,50.446 37.3,50.446 38.8,50.446 40.3,50.446 41.8,50.446 1.255,50.454 2.755,50.454 4.255,50.454 5.755,50.454 7.255,50.454 8.755,50.454 10.255,50.454 12.72,50.716 14.988,50.716 16.13,50.716 18.058,50.716 19.145,50.716 21.5,50.716
GPIO3/BOOT0: CN1.9 R1.1 U1.34 | length 40.5
  Top Layer w0.2: v1(10.447,27.715) 10.447,27.823 11.05,28.426 11.05,28.945 11.205,29.1 R1.1@11.3,29.1 ; U1.34@19.711,35.378 19.747,35.414 19.747,35.793 20.4,36.447 20.4,37.168 v1(20.907,37.675)
  Internal 1 w0.2: v1(10.447,27.715) 10.447,27.151 13.097,24.501 21.007,24.501 22.688,26.182 22.688,35.166 20.907,36.947 v1(20.907,37.675)
  Bottom Layer w0.2: CN1.9@2.335,28.713 3.854,28.713 4.504,29.363 8.604,29.363 10.176,27.792 10.371,27.792 v1(10.447,27.715)
GPIO5/JTMS/SWDIO: CN1.13 R2.2 U1.27 | length 56.6
  Top Layer w0.2: v1(8.445,26.863) 8.34,26.863 8.202,26.725 8.132,26.725 6.607,25.2 6.607,20.622 13.605,13.624 15.299,13.624 15.793,13.13 15.793,12.126 18.384,9.534 v1(18.384,8.141) ; U1.27@23.211,35.378 23.256,35.423 23.256,35.838 23.45,36.032 23.45,36.453 23.733,36.735 v1(23.733,36.841)
  Bottom Layer w0.2: CN1.13@2.335,26.173 3.939,26.173 4.541,26.775 4.875,26.775 4.919,26.82 7.902,26.82 7.945,26.863 v1(8.445,26.863) 10.939,26.863 13.251,29.175 14.452,29.175 14.469,29.192 16.816,29.192 17.804,30.18 21.072,30.18 23.487,32.594 23.487,36.489 23.733,36.735 v1(23.733,36.841) ; v1(18.384,8.141) 18.459,8.066 18.459,7.579 18.88,7.158 R2.2@18.975,7.158
GPIO6/JTCK/SWCLK: CN1.15 R3.2 U1.26 | length 60.9
  Top Layer w0.2: v1(9.512,26.271) 9.468,26.227 9.083,26.227 7.675,24.819 7.675,20.621 13.037,15.26 14.79,15.26 16.788,13.262 16.788,12.69 16.757,12.66 16.757,12.264 19.845,9.177 19.845,8.299 v1(19.83,8.285) ; U1.26@23.711,35.378 23.756,35.423 23.756,35.728 24.066,36.037 v1(24.066,36.143)
  Internal 1 w0.2: v1(9.512,26.271) 10.551,26.271 12.671,24.151 21.449,24.151 23.289,25.992 23.289,35.366 v1(24.066,36.143)
  Bottom Layer w0.2: CN1.15@2.335,24.903 3.695,24.903 4.336,25.544 8.052,25.544 8.779,26.271 v1(9.512,26.271) ; v1(19.83,8.285) 19.83,8.203 20.211,7.821 R3.2@20.211,7.176
GPIO11: CN1.24 SB46.1 | length 14.3
  Top Layer w0.2: v1(10.004,19.638) 10.081,19.714 10.283,19.714 10.321,19.752 16.873,19.752 v1(18.225,18.4)
  Bottom Layer w0.2: CN1.24@6.399,19.823 6.443,19.779 9.304,19.779 9.404,19.679 9.963,19.679 v1(10.004,19.638) ; v1(18.225,18.4) 18.25,18.425 19.825,18.425 19.92,18.52 SB46.1@19.932,18.52
GPIO12: CN1.47 R8.2 SB44.1 | length 28.5
  Internal 1 w0.2: v1(16.324,3.325) 16.399,3.25 16.612,3.25 16.798,3.065 24.463,3.065 26.197,4.799 v1(26.197,6.989)
  Bottom Layer w0.2: CN1.47@2.335,4.583 2.421,4.497 4.178,4.497 4.711,3.965 7.867,3.965 7.933,3.898 SB44.1@8.629,3.898 8.629,3.883 8.867,3.646 8.867,3.444 9.013,3.298 16.297,3.298 v1(16.324,3.325) ; R8.2@25.31,7.158 26.042,7.158 26.197,7.003 v1(26.197,6.989)
GPIO13: CN1.26 SB9.1 | length 12.7
  Top Layer w0.2: v1(8.075,18.345) 8.165,18.345 9.729,16.781 v1(9.729,9.27)
  Bottom Layer w0.2: CN1.26@6.399,18.553 6.607,18.345 v1(8.075,18.345) ; v1(9.729,9.27) 10.35,8.649 10.35,8.551 10.464,8.437 SB9.1@10.464,8.425
GPIO14: CN1.29 SB30.1 | length 27.1
  Internal 1 w0.2: v1(4.3,16) 6.773,18.473 6.773,22.303 8.271,23.801 21.831,23.801 22.595,23.037 22.885,23.037 v1(22.962,22.96)
  Bottom Layer w0.2: CN1.29@2.335,16.013 2.348,16 v1(4.3,16) ; v1(22.962,22.96) SB30.1@23.568,22.96
GPIO15/OSC32_IN: CN1.33 SB37.2 | length 46
  Top Layer w0.2: v1(21.44,21.262) 21.511,21.19 21.511,18.892 21.438,18.819 21.438,13.552 21.672,13.318 v1(22.157,13.318)
  Internal 1 w0.2: v1(4.367,13.447) 4.361,13.44 4.361,12.747 6.239,10.869 19.542,10.869 21.849,13.176 21.91,13.176 22.051,13.318 v1(22.157,13.318)
  Bottom Layer w0.2: CN1.33@2.335,13.473 2.361,13.447 v1(4.367,13.447) ; v1(21.44,21.262) 21.44,21.322 22.192,22.074 22.192,24.97 23.422,26.2 24.565,26.2 28.742,30.377 28.742,31.76 28.117,32.385 28.107,32.385 28.085,32.407 SB37.2@28.073,32.407
GPIO16/OSC32_OUT: CN1.35 SB38.2 | length 45.3
  Top Layer w0.2: v1(20.252,21.273) 20.943,20.582 20.943,18.819 20.822,18.698 20.822,13.412 21.708,12.526 22.373,12.526 v1(22.38,12.533)
  Internal 1 w0.2: v1(4.332,11.705) 4.408,11.628 4.655,11.628 5.89,10.393 9.587,10.393 9.591,10.389 19.874,10.389 21.975,12.49 22.337,12.49 v1(22.38,12.533)
  Bottom Layer w0.2: CN1.35@2.335,12.203 3.982,12.203 4.354,11.831 4.332,11.809 v1(4.332,11.705) ; v1(20.252,21.273) 20.325,21.346 20.325,23.82 23.08,26.575 24.157,26.575 27.792,30.21 27.792,30.5 27.947,30.655 27.993,30.655 28.088,30.75 SB38.2@28.1,30.75
GPIO17: CN1.36 SB8.1 | length 4.6
  Bottom Layer w0.2: CN1.36@6.399,12.203 6.417,12.185 8.743,12.185 9.729,11.199 SB8.1@10.538,11.199 ; 10.451,11.401 10.465,11.386 10.515,11.386 10.526,11.376
GPIO18: CN2.45 SB18.1 | length 4.1
  Bottom Layer w0.2: SB18.1@32.547,5.853 CN2.45@36.625,5.853
GPIO19: CN2.15 SB23.1 | length 3.3
  Bottom Layer w0.2: SB23.1@33.332,24.903 CN2.15@36.625,24.903
GPIO20: CN1.38 SB16.1 | length 4.5
  Bottom Layer w0.2: CN1.38@6.399,10.933 6.432,10.9 8.218,10.9 9.293,9.825 SB16.1@10.476,9.825
GPIO21: CN2.21 SB17.1 | length 3.8
  Bottom Layer w0.2: 33.325,21.6 33.325,21.615 33.4,21.69 33.4,21.861 34.023,21.861 34.791,21.093 CN2.21@36.625,21.093
GPIO22: CN1.44 SB14.1 | length 4.2
  Bottom Layer w0.2: CN1.44@6.399,7.123 9.584,7.123 10.246,7.123 10.462,7.339
GPIO23: CN2.11 SB21.1 | length 3.3
  Bottom Layer w0.2: SB21.1@33.301,27.458 36.61,27.458 CN2.11@36.625,27.443
GPIO24: CN2.39 U1.4 | length 34.9
  Top Layer w0.2: U1.4@20.211,28.628 20.242,28.598 20.242,28.053 20.354,27.941 20.354,25.984 20.713,25.625 20.713,23.734 19.724,22.746 19.722,22.746 18.847,21.87 18.847,14.605 21.634,11.817 v1(22.717,11.817)
  Bottom Layer w0.2: v1(22.717,11.817) 25.039,11.817 27.271,9.585 36.547,9.585 CN2.39@36.625,9.663
GPIO25: CN2.42 SB7.1 | length 8.6
  Bottom Layer w0.2: SB7.1@32.525,7.339 32.533,7.347 32.592,7.347 32.595,7.35 33.644,7.35 34.041,7.747 38.105,7.747 38.751,8.393 CN2.42@40.689,8.393
GPIO26: CN1.42 SB45.1 | length 2.2
  Bottom Layer w0.2: CN1.42@6.399,8.393 8.322,8.393 8.535,8.606
GPIO27: CN2.35 SB12.1 | length 4.5
  Bottom Layer w0.2: SB12.1@32.525,12.5 32.525,12.495 32.595,12.425 34.203,12.425 34.425,12.203 CN2.35@36.625,12.203 CN2.35@36.403,12.425
GPIO28: CN2.7 SB22.2 | length 3.6
  Bottom Layer w0.2: SB22.2@33.414,30.79 33.428,30.79 33.463,30.825 34.21,30.825 35.045,29.99 36.618,29.99 CN2.7@36.625,29.983
GPIO29: CN2.23 SB48.1 | length 2.7
  Bottom Layer w0.2: SB48.1@33.323,20.678 34.126,19.875 35.545,19.875 CN2.23@35.625,19.794
GPIO30: CN2.10 SB13.2 | length 7.9
  Bottom Layer w0.2: SB13.2@33.377,28.774 33.6,28.774 34.28,28.095 38.126,28.095 38.718,28.687 40.663,28.687 CN2.10@40.689,28.713
GPIO31: CN2.13 SB10.2 | length 3.2
  Bottom Layer w0.2: SB10.2@33.413,26.173 SB10.2@33.425,26.173 33.452,26.201 36.597,26.201 CN2.13@36.625,26.173
GPIO32: CN2.12 R4.2 U1.24 | length 57.6
  Top Layer w0.2: U1.24@24.836,34.753 24.961,34.753 25.011,34.803 25.011,34.925 26.102,36.015 26.102,36.187 v1(26.178,36.264)
  Internal 1 w0.2: v1(21.88,8.322) 22.54,7.661 25.326,7.661 28.754,11.09 28.754,16.134 32.445,19.824 33.047,19.824 v1(33.1,19.878)
  Internal 2 w0.2: v1(33.1,19.878) 33.1,19.912 34.755,21.567 37.362,21.567 39.05,23.255 39.05,26.433 38.744,26.738 v1(38.744,26.844)
  Bottom Layer w0.2: R4.2@21.49,7.158 21.49,7.863 21.88,8.253 v1(21.88,8.322) ; v1(26.178,36.264) 26.286,36.264 26.485,36.462 28.571,36.462 31.802,33.231 31.802,31.15 30.85,30.197 30.85,27.56 31.608,26.802 38.702,26.802 39.15,27.25 40.496,27.25 CN2.12@40.689,27.443
GPIO33: CN2.29 SB47.1 | length 13.5
  Bottom Layer w0.2: SB47.1@24.311,16.809 24.951,16.17 28.155,16.17 29.4,14.925 30.731,14.925 31.756,15.95 36.562,15.95 CN2.29@36.625,16.013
